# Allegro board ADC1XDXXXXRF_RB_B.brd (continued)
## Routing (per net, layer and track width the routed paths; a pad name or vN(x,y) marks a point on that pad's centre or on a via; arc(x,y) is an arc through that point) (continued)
FMC_DID-4: length 142.1
  TOP w0.102: v1(115.72,88.75) U5.T3
  SIG2 w0.102: v1(115.72,88.75) 115.32,88.34 102.93,88.34 101.92,89.35 83.81,89.35 83.71,89.45 83.71,89.52 83.48,89.74 83.11,89.74 82.89,89.52 82.89,89.45 82.79,89.35 82.59,89.35 82.49,89.45 82.49,89.52 82.27,89.74 81.89,89.74 81.67,89.52 81.67,89.45 81.57,89.35 81.37,89.35 81.27,89.45 81.27,89.52 81.05,89.74 80.67,89.74 80.45,89.52 80.45,89.45 80.35,89.35 80.15,89.35 80.05,89.45 80.05,89.52 79.83,89.74 79.46,89.74 79.23,89.52 79.23,89.45 79.13,89.35 78.37,89.35 77.93,88.9 77.93,88.08 77.83,87.98 76.7,87.98 76.48,87.76 76.48,87.39 76.7,87.17 77.83,87.17 77.93,87.06 77.93,86.86 77.83,86.76 76.7,86.76 76.48,86.54 76.48,86.17 76.7,85.95 77.83,85.95 77.93,85.85 77.93,84.94 77.62,84.63 75.13,84.63 75.03,84.73 75.03,85.1 74.81,85.32 74.44,85.32 74.22,85.1 74.22,84.73 74.12,84.63 73.91,84.63 73.81,84.73 73.81,85.1 73.59,85.32 73.22,85.32 73,85.1 73,84.73 72.9,84.63 72.69,84.63 72.59,84.73 72.59,85.1 72.37,85.32 72,85.32 71.78,85.1 71.78,84.73 71.68,84.63 71.48,84.63 71.37,84.73 71.37,85.1 71.15,85.32 70.78,85.32 70.56,85.1 70.56,84.73 70.46,84.63 70.26,84.63 70.15,84.73 70.15,85.1 69.93,85.32 69.56,85.32 69.34,85.1 69.34,84.73 69.24,84.63 69.04,84.63 68.94,84.73 68.94,85.1 68.72,85.32 68.34,85.32 68.12,85.1 68.12,84.73 68.02,84.63 67.82,84.63 67.72,84.73 67.72,85.1 67.5,85.32 67.12,85.32 66.9,85.1 66.9,84.73 66.8,84.63 66.6,84.63 66.5,84.73 66.5,85.1 66.28,85.32 65.9,85.32 65.68,85.1 65.68,84.73 65.58,84.63 65.38,84.63 65.28,84.73 65.28,85.1 65.06,85.32 64.69,85.32 64.47,85.1 64.47,84.73 64.36,84.63 64.16,84.63 64.06,84.73 64.06,85.1 63.84,85.32 63.47,85.32 63.25,85.1 63.25,84.73 63.14,84.63 62.94,84.63 62.84,84.73 62.84,85.1 62.62,85.32 62.25,85.32 62.03,85.1 62.03,84.73 61.93,84.63 61.72,84.63 61.62,84.73 61.62,85.1 61.4,85.32 61.03,85.32 60.81,85.1 60.81,84.73 60.71,84.63 60.5,84.63 60.4,84.73 60.4,85.1 60.18,85.32 59.81,85.32 59.59,85.1 59.59,84.73 59.49,84.63 59.28,84.63 59.18,84.73 59.18,85.1 58.96,85.32 58.59,85.32 58.37,85.1 58.37,84.73 58.27,84.63 58.06,84.63 57.96,84.73 57.96,85.1 57.74,85.32 57.37,85.32 57.15,85.1 57.15,84.73 57.05,84.63 56.85,84.63 56.74,84.73 56.74,85.1 56.52,85.32 56.15,85.32 55.93,85.1 55.93,84.73 55.83,84.63 55.63,84.63 55.52,84.73 55.52,85.1 55.3,85.32 54.93,85.32 54.71,85.1 54.71,84.73 54.61,84.63 54.41,84.63 54.31,84.73 54.31,85.1 54.08,85.32 53.71,85.32 53.49,85.1 53.49,84.73 53.39,84.63 53.19,84.63 53.09,84.73 53.09,85.1 52.87,85.32 52.49,85.32 52.27,85.1 52.27,84.73 52.17,84.63 51.97,84.63 51.87,84.73 51.87,85.1 51.65,85.32 51.27,85.32 51.05,85.1 51.05,84.73 50.95,84.63 50.75,84.63 50.65,84.73 50.65,85.1 50.43,85.32 50.06,85.32 49.83,85.1 49.83,84.73 49.73,84.63 49.53,84.63 49.43,84.73 49.43,85.1 49.21,85.32 48.84,85.32 48.62,85.1 48.62,84.73 48.51,84.63 48.31,84.63 48.21,84.73 48.21,85.1 47.99,85.32 47.62,85.32 47.4,85.1 47.4,84.73 47.29,84.63 47.09,84.63 46.99,84.73 46.99,85.1 46.77,85.32 46.4,85.32 46.18,85.1 46.18,84.73 46.08,84.63 11.33,84.63 v3(10.79,85.17)
  BOTTOM w0.102: FMC.D12 v3(10.79,85.17)
FMC_DID-5: length 142.2
  TOP w0.102: v1(114.72,87.74) U5.U2
  SIG2 w0.102: v3(9.53,83.9) 10.06,83.36 46.08,83.36 46.18,83.46 46.18,83.8 46.4,84.02 46.77,84.02 46.99,83.8 46.99,83.46 47.09,83.36 47.29,83.36 47.4,83.46 47.4,83.8 47.62,84.02 47.99,84.02 48.21,83.8 48.21,83.46 48.31,83.36 48.51,83.36 48.62,83.46 48.62,83.8 48.84,84.02 49.21,84.02 49.43,83.8 49.43,83.46 49.53,83.36 49.73,83.36 49.83,83.46 49.83,83.8 50.06,84.02 50.43,84.02 50.65,83.8 50.65,83.46 50.75,83.36 50.95,83.36 51.05,83.46 51.05,83.8 51.27,84.02 51.65,84.02 51.87,83.8 51.87,83.46 51.97,83.36 52.17,83.36 52.27,83.46 52.27,83.8 52.49,84.02 52.87,84.02 53.09,83.8 53.09,83.46 53.19,83.36 53.39,83.36 53.49,83.46 53.49,83.8 53.71,84.02 54.08,84.02 54.31,83.8 54.31,83.46 54.41,83.36 54.61,83.36 54.71,83.46 54.71,83.8 54.93,84.02 55.3,84.02 55.52,83.8 55.52,83.46 55.63,83.36 55.83,83.36 55.93,83.46 55.93,83.8 56.15,84.02 56.52,84.02 56.74,83.8 56.74,83.46 56.85,83.36 57.05,83.36 57.15,83.46 57.15,83.8 57.37,84.02 57.74,84.02 57.96,83.8 57.96,83.46 58.06,83.36 58.27,83.36 58.37,83.46 58.37,83.8 58.59,84.02 58.96,84.02 59.18,83.8 59.18,83.46 59.28,83.36 59.49,83.36 59.59,83.46 59.59,83.8 59.81,84.02 60.18,84.02 60.4,83.8 60.4,83.46 60.5,83.36 62.64,83.36 62.75,83.46 62.75,83.8 62.97,84.02 63.34,84.02 63.56,83.8 63.56,83.46 63.66,83.36 63.86,83.36 63.96,83.46 63.96,83.8 64.19,84.02 64.56,84.02 64.78,83.8 64.78,83.46 64.88,83.36 65.08,83.36 65.18,83.46 65.18,83.8 65.4,84.02 65.78,84.02 66,83.8 66,83.46 66.1,83.36 66.3,83.36 66.4,83.46 66.4,83.8 66.62,84.02 67,84.02 67.22,83.8 67.22,83.46 67.32,83.36 67.52,83.36 67.62,83.46 67.62,83.8 67.84,84.02 68.21,84.02 68.43,83.8 68.43,83.46 68.54,83.36 68.74,83.36 68.84,83.46 68.84,83.8 69.06,84.02 69.43,84.02 69.65,83.8 69.65,83.46 69.76,83.36 69.96,83.36 70.06,83.46 70.06,83.8 70.28,84.02 70.65,84.02 70.87,83.8 70.87,83.46 70.97,83.36 71.18,83.36 71.28,83.46 71.28,83.8 71.5,84.02 71.87,84.02 72.09,83.8 72.09,83.46 72.19,83.36 72.4,83.36 72.5,83.46 72.5,83.8 72.72,84.02 73.09,84.02 73.31,83.8 73.31,83.46 73.41,83.36 73.62,83.36 73.72,83.46 73.72,83.8 73.94,84.02 74.31,84.02 74.53,83.8 74.53,83.46 74.63,83.36 74.84,83.36 74.94,83.46 74.94,83.8 75.16,84.02 75.53,84.02 75.75,83.8 75.75,83.46 75.85,83.36 76.05,83.36 76.16,83.46 76.16,83.8 76.38,84.02 76.75,84.02 76.97,83.8 76.97,83.46 77.07,83.36 77.67,83.36 79.2,84.89 79.2,86.42 79.42,86.64 83.31,86.64 83.41,86.74 83.41,86.95 83.31,87.05 79.42,87.05 79.2,87.27 79.2,87.94 79.6,88.34 101.7,88.34 102.7,87.34 114.33,87.34 114.72,87.73 v1(114.72,87.74)
  BOTTOM w0.102: FMC.C11 v3(9.53,83.9)
FMC_DID-6: length 142.1
  TOP w0.102: v1(113.72,86.74) U5.V1
  SIG3 w0.102: v1(113.72,86.74) 113.82,86.64 114.17,86.64 114.3,86.77 114.3,86.87 114.03,87.14 77.71,87.14 76.89,86.31 76.89,85.75 76.96,85.67 77.45,85.67 77.57,85.55 77.57,85.39 v3(77.34,85.17)
  BOTTOM w0.102: FMC.H14 17.27,87.83 52.17,87.83 56.62,92.28 64.29,92.28 65,91.57 65,70.62 65.54,70.08 74.57,70.08 74.83,70.34 74.83,85.81 75.31,86.28 76.66,86.28 77.14,85.81 77.14,85.37 v3(77.34,85.17)
FMC_DID-7: length 142.1
  TOP w0.102: U5.P6 119.2,91.24 v1(118.71,90.75)
  SIG1 w0.102: v1(118.71,90.75) 118.83,90.75 119.1,90.47 119.1,89.56 118.88,89.34 117.43,89.34 117.12,89.04 117.12,88.55 116.91,88.34 105.24,88.34 97.52,96.06 58.06,96.06 57.96,96.16 57.96,96.4 57.74,96.62 57.36,96.62 57.14,96.4 57.14,96.16 57.04,96.06 56.84,96.06 56.74,96.16 56.74,96.4 56.52,96.62 56.15,96.62 55.92,96.4 55.92,96.16 55.82,96.06 55.62,96.06 55.52,96.16 55.52,96.4 55.3,96.62 54.93,96.62 54.71,96.4 54.71,96.16 54.6,96.06 54.4,96.06 54.3,96.16 54.3,96.4 54.08,96.62 53.71,96.62 53.49,96.4 53.49,96.16 53.38,96.06 53.18,96.06 53.08,96.16 53.08,96.4 52.86,96.62 52.49,96.62 52.27,96.4 52.27,96.16 52.17,96.06 51.96,96.06 51.86,96.16 51.86,96.4 51.64,96.62 51.27,96.62 51.05,96.4 51.05,96.16 50.95,96.06 50.74,96.06 50.64,96.16 50.64,96.4 50.42,96.62 50.05,96.62 49.83,96.4 49.83,96.16 49.73,96.06 49.52,96.06 49.42,96.16 49.42,96.4 49.2,96.62 48.83,96.62 48.61,96.4 48.61,96.16 48.51,96.06 48.3,96.06 48.2,96.16 48.2,96.4 47.98,96.62 47.61,96.62 47.39,96.4 47.39,96.16 47.29,96.06 47.09,96.06 46.98,96.16 46.98,96.4 46.76,96.62 46.39,96.62 46.17,96.4 46.17,96.16 46.07,96.06 11.75,96.06 11.12,95.43 9.75,95.43 8.76,94.45 8.76,88.51 9.03,88.24 15.44,88.24 15.77,87.9 15.77,86.24 15.44,85.9 14.68,85.9 14.61,85.98 v3(14.61,86.44)
  BOTTOM w0.102: FMC.G13 v3(14.61,86.44)
FMC_DID-8: length 142.1
  TOP w0.102: v1(115.72,89.75) U5.R3
  SIG2 w0.102: v1(115.72,89.75) 115.6,89.75 114.99,90.35 103.46,90.35 102.46,91.35 76.26,91.35 72.66,87.76 58.06,87.76 57.96,87.86 57.96,89.37 57.74,89.59 57.37,89.59 57.15,89.37 57.15,87.86 57.05,87.76 56.85,87.76 56.74,87.86 56.74,89.37 56.52,89.59 56.15,89.59 55.93,89.37 55.93,87.86 55.83,87.76 55.63,87.76 55.52,87.86 55.52,89.37 55.3,89.59 54.93,89.59 54.71,89.37 54.71,87.86 54.61,87.76 54.41,87.76 54.31,87.86 54.31,89.37 54.08,89.59 53.71,89.59 53.49,89.37 53.49,87.86 53.39,87.76 53.19,87.76 53.09,87.86 53.09,89.37 52.87,89.59 52.49,89.59 52.27,89.37 52.27,87.86 52.17,87.76 51.97,87.76 51.87,87.86 51.87,89.37 51.65,89.59 51.27,89.59 51.05,89.37 51.05,87.86 50.95,87.76 50.75,87.76 50.65,87.86 50.65,89.37 50.43,89.59 50.06,89.59 49.83,89.37 49.83,87.86 49.73,87.76 49.53,87.76 49.43,87.86 49.43,89.37 49.21,89.59 48.84,89.59 48.62,89.37 48.62,87.86 48.51,87.76 48.31,87.76 48.21,87.86 48.21,89.37 47.99,89.59 47.62,89.59 47.4,89.37 47.4,87.86 47.29,87.76 47.09,87.76 46.99,87.86 46.99,89.37 46.77,89.59 46.4,89.59 46.18,89.37 46.18,87.86 46.08,87.76 16.24,87.76 15.55,88.44 11.58,88.44 11.51,88.52 11.51,88.9 11.58,88.98 v3(12.06,88.98)
  BOTTOM w0.102: FMC.D15 v3(12.06,88.98)
FMC_DID-9: length 142.1
  TOP w0.102: v1(113.72,89.75) U5.R1
  SIG2 w0.102: v3(10.79,87.71) 10.52,87.71 10.44,87.63 10.44,87.25 10.52,87.17 13.55,87.17 14,86.72 14,86.19 14.26,85.93 46.08,85.93 46.18,86.03 46.18,86.93 46.4,87.15 46.77,87.15 46.99,86.93 46.99,86.03 47.09,85.93 47.29,85.93 47.4,86.03 47.4,86.93 47.62,87.15 47.99,87.15 48.21,86.93 48.21,86.03 48.31,85.93 48.51,85.93 48.62,86.03 48.62,86.93 48.84,87.15 49.21,87.15 49.43,86.93 49.43,86.03 49.53,85.93 49.73,85.93 49.83,86.03 49.83,86.93 50.06,87.15 50.43,87.15 50.65,86.93 50.65,86.03 50.75,85.93 50.95,85.93 51.05,86.03 51.05,86.93 51.27,87.15 51.65,87.15 51.87,86.93 51.87,86.03 51.97,85.93 52.17,85.93 52.27,86.03 52.27,86.93 52.49,87.15 52.87,87.15 53.09,86.93 53.09,86.03 53.19,85.93 53.39,85.93 53.49,86.03 53.49,86.93 53.71,87.15 54.08,87.15 54.31,86.93 54.31,86.03 54.41,85.93 54.61,85.93 54.71,86.03 54.71,86.93 54.93,87.15 55.3,87.15 55.52,86.93 55.52,86.03 55.63,85.93 58.28,85.93 58.39,86.03 58.39,86.83 58.61,87.05 58.98,87.05 59.2,86.83 59.2,86.03 59.3,85.93 59.5,85.93 59.6,86.03 59.6,86.83 59.83,87.05 60.2,87.05 60.42,86.83 60.42,86.03 60.52,85.93 60.72,85.93 60.82,86.03 60.82,86.83 61.04,87.05 61.42,87.05 61.64,86.83 61.64,86.03 61.74,85.93 61.94,85.93 62.04,86.03 62.04,86.83 62.26,87.05 62.64,87.05 62.86,86.83 62.86,86.03 62.96,85.93 63.16,85.93 63.26,86.03 63.26,86.83 63.48,87.05 63.85,87.05 64.08,86.83 64.08,86.03 64.18,85.93 64.38,85.93 64.48,86.03 64.48,86.83 64.7,87.05 65.07,87.05 65.29,86.83 65.29,86.03 65.4,85.93 65.6,85.93 65.7,86.03 65.7,86.8 65.92,87.02 66.29,87.02 66.51,86.8 66.51,86.03 66.62,85.93 66.82,85.93 66.92,86.03 66.92,86.8 67.14,87.02 67.51,87.02 67.73,86.8 67.73,86.03 67.83,85.93 68.04,85.93 68.14,86.03 68.14,86.8 68.36,87.02 68.73,87.02 68.95,86.8 68.95,86.03 69.05,85.93 73.6,85.93 78.02,90.35 102.17,90.35 103.17,89.35 113.58,89.35 113.72,89.49 v1(113.72,89.75)
  BOTTOM w0.102: FMC.C15 v3(10.79,87.71)
FMC_DID-10: length 142.2
  TOP w0.102: v1(116.71,90.75) 117.2,91.24 U5.P4
  SIG2 w0.102: v1(116.71,90.75) 116.71,90.76 116.11,91.35 103.67,91.35 102.66,92.35 64.38,92.35 64.27,92.46 64.27,93.68 64.05,93.9 63.68,93.9 63.46,93.68 63.46,92.46 63.36,92.35 63.16,92.35 63.05,92.46 63.05,93.68 62.83,93.9 62.46,93.9 62.24,93.68 62.24,92.46 62.14,92.35 61.94,92.35 61.84,92.46 61.84,93.68 61.62,93.9 61.24,93.9 61.02,93.68 61.02,92.46 60.92,92.35 60.72,92.35 60.62,92.46 60.62,93.68 60.4,93.9 60.02,93.9 59.8,93.68 59.8,92.46 59.7,92.35 59.5,92.35 59.4,92.46 59.4,93.68 59.18,93.9 58.8,93.9 58.58,93.68 58.58,92.46 58.48,92.35 58.28,92.35 58.18,92.46 58.18,93.68 57.96,93.9 57.59,93.9 57.37,93.68 57.37,92.46 57.26,92.35 57.06,92.35 56.96,92.46 56.96,93.68 56.74,93.9 56.37,93.9 56.15,93.68 56.15,92.46 56.04,92.35 55.84,92.35 55.74,92.46 55.74,93.68 55.52,93.9 55.15,93.9 54.93,93.68 54.93,92.46 54.83,92.35 54.62,92.35 54.52,92.46 54.52,93.68 54.3,93.9 53.93,93.9 53.71,93.68 53.71,92.46 53.61,92.35 53.4,92.35 53.3,92.46 53.3,93.68 53.08,93.9 52.71,93.9 52.49,93.68 52.49,92.46 52.39,92.35 52.18,92.35 52.08,92.46 52.08,93.68 51.86,93.9 51.49,93.9 51.27,93.68 51.27,92.46 51.17,92.35 50.96,92.35 50.86,92.46 50.86,93.68 50.64,93.9 50.27,93.9 50.05,93.68 50.05,92.46 49.95,92.35 49.75,92.35 49.64,92.46 49.64,93.68 49.42,93.9 49.05,93.9 48.83,93.68 48.83,92.46 48.73,92.35 48.53,92.35 48.42,92.46 48.42,93.68 48.2,93.9 47.83,93.9 47.61,93.68 47.61,92.46 47.51,92.35 46.78,92.35 45.41,90.98 16.64,90.98 16.54,91.08 16.54,91.41 16.64,91.52 v3(17.14,91.52)
  BOTTOM w0.102: v3(17.14,91.52) FMC.H17
FMC_DID-11: length 142.1
  TOP w0.102: U5.P2 115.2,91.24 v1(114.7,90.75)
  SIG3 w0.102: v1(114.7,90.75) 114.97,90.75 115.11,90.6 115.11,90.47 114.99,90.35 76.37,90.35 75,88.98 v3(74.96,88.98)
  BOTTOM w0.102: v3(74.96,88.98) 75.16,88.77 75.16,88.44 73.56,86.84 73.56,71.91 73.07,71.42 66.63,71.42 66.27,71.78 66.27,92.99 65.71,93.55 56.08,93.55 51.64,89.1 15.65,89.1 15.24,89.51 FMC.G16
FMC_DQ+0: length 142
  TOP w0.102: U5.C4 117.22,102.25 v1(116.71,102.76)
  SIG2 w0.102: v1(116.71,102.76) 116.71,102.44 116.62,102.36 103.82,102.36 94.88,111.3 61.72,111.3 61.62,111.4 61.62,111.62 61.4,111.84 61.03,111.84 60.81,111.62 60.81,111.4 60.71,111.3 60.5,111.3 60.4,111.4 60.4,111.62 60.18,111.84 59.81,111.84 59.59,111.62 59.59,111.4 59.49,111.3 59.28,111.3 59.18,111.4 59.18,111.62 58.96,111.84 58.59,111.84 58.37,111.62 58.37,111.4 58.27,111.3 58.06,111.3 57.96,111.4 57.96,111.62 57.74,111.84 57.37,111.84 57.15,111.62 57.15,111.4 57.05,111.3 56.85,111.3 56.74,111.4 56.74,111.62 56.52,111.84 56.15,111.84 55.93,111.62 55.93,111.4 55.83,111.3 55.63,111.3 55.52,111.4 55.52,111.62 55.3,111.84 54.93,111.84 54.71,111.62 54.71,111.4 54.61,111.3 54.41,111.3 54.31,111.4 54.31,111.62 54.08,111.84 53.71,111.84 53.49,111.62 53.49,111.4 53.39,111.3 53.19,111.3 53.09,111.4 53.09,111.62 52.87,111.84 52.49,111.84 52.27,111.62 52.27,111.4 52.17,111.3 51.97,111.3 51.87,111.4 51.87,111.62 51.65,111.84 51.27,111.84 51.05,111.62 51.05,111.4 50.95,111.3 50.75,111.3 50.65,111.4 50.65,111.62 50.43,111.84 50.06,111.84 49.83,111.62 49.83,111.4 49.73,111.3 49.53,111.3 49.43,111.4 49.43,111.62 49.21,111.84 48.84,111.84 48.62,111.62 48.62,111.4 48.51,111.3 48.31,111.3 48.21,111.4 48.21,111.62 47.99,111.84 47.62,111.84 47.4,111.62 47.4,111.4 47.29,111.3 47.09,111.3 46.99,111.4 46.99,111.62 46.77,111.84 46.4,111.84 46.18,111.62 46.18,111.4 46.08,111.3 9.87,111.3 8.79,110.22 8.79,101.21 9.06,100.94 12.29,100.94 12.6,100.63 12.6,100.02 12.95,99.67 17.14,99.67 17.25,99.57 17.25,99.24 v3(17.14,99.14)
  BOTTOM w0.102: v3(17.14,99.14) FMC.J24
FMC_DQ+1: length 142.2
  TOP w0.102: v1(117.71,102.76) 118.22,102.25 U5.C5
  SIG1 w0.102: v3(13.34,97.87) 12.8,98.4 9.06,98.4 8.79,98.67 8.79,117.36 9.09,117.65 103.67,117.65 116.31,105.01 116.31,102.59 116.54,102.36 117.31,102.36 v1(117.71,102.76)
  BOTTOM w0.102: FMC.F22 v3(13.34,97.87)
FMC_DQ+2: length 142
  TOP w0.102: U5.E6 119.22,100.24 v1(118.71,100.75)
  SIG2 w0.102: v1(118.71,100.75) 118.31,101.15 118.31,103.06 118.01,103.36 104.02,103.36 94.8,112.57 50.75,112.57 50.65,112.67 50.65,112.91 50.43,113.13 50.06,113.13 49.83,112.91 49.83,112.67 49.73,112.57 49.53,112.57 49.43,112.67 49.43,112.91 49.21,113.13 48.84,113.13 48.62,112.91 48.62,112.67 48.51,112.57 48.31,112.57 48.21,112.67 48.21,112.91 47.99,113.13 47.62,113.13 47.4,112.91 47.4,112.67 47.29,112.57 47.09,112.57 46.99,112.67 46.99,112.91 46.77,113.13 46.4,113.13 46.18,112.91 46.18,112.67 46.08,112.57 8.83,112.57 7.52,111.26 7.52,98.12 9.42,96.22 9.42,95.62 9.82,95.22 10.4,95.22 11.02,95.85 11.53,95.85 v3(12.06,95.31)
  BOTTOM w0.102: FMC.E21 v3(12.06,95.31)
FMC_DQ+3: length 142.2
  TOP w0.102: v1(118.72,97.74) U5.G6
  SIG2 w0.102: v3(14.61,100.41) 14,100.41 13.84,100.56 13.84,100.81 13.97,100.94 46.16,100.94 46.38,101.16 46.38,101.37 46.48,101.47 46.69,101.47 46.79,101.37 46.79,101.16 47.01,100.94 47.38,100.94 47.6,101.16 47.6,101.37 47.7,101.47 47.9,101.47 48.01,101.37 48.01,101.16 48.23,100.94 48.6,100.94 48.82,101.16 48.82,101.37 48.92,101.47 49.12,101.47 49.23,101.37 49.23,101.16 49.45,100.94 49.82,100.94 50.04,101.16 50.04,101.37 50.14,101.47 50.34,101.47 50.44,101.37 50.44,101.16 50.66,100.94 51.04,100.94 51.26,101.16 51.26,101.37 51.36,101.47 51.56,101.47 51.66,101.37 51.66,101.16 51.88,100.94 52.26,100.94 52.48,101.16 52.48,101.37 52.58,101.47 52.78,101.47 52.88,101.37 52.88,101.16 53.1,100.94 53.48,100.94 53.7,101.16 53.7,101.37 53.8,101.47 54,101.47 54.1,101.37 54.1,101.16 54.32,100.94 54.69,100.94 54.91,101.16 54.91,101.37 55.02,101.47 55.22,101.47 55.32,101.37 55.32,101.16 55.54,100.94 55.91,100.94 56.13,101.16 56.13,101.37 56.24,101.47 56.44,101.47 56.54,101.37 56.54,101.16 56.76,100.94 57.13,100.94 57.35,101.16 57.35,101.37 57.45,101.47 57.66,101.47 57.76,101.37 57.76,101.16 57.98,100.94 58.35,100.94 58.57,101.16 58.57,101.37 58.67,101.47 58.88,101.47 58.98,101.37 58.98,101.16 59.2,100.94 59.57,100.94 59.79,101.16 59.79,101.37 59.89,101.47 60.1,101.47 60.2,101.37 60.2,101.16 60.42,100.94 60.79,100.94 61.01,101.16 61.01,101.37 61.11,101.47 61.32,101.47 61.42,101.37 61.42,101.16 61.64,100.94 62.01,100.94 62.23,101.16 62.23,101.37 62.33,101.47 62.53,101.47 62.64,101.37 62.64,101.16 62.86,100.94 63.23,100.94 63.45,101.16 63.45,101.37 63.55,101.47 63.75,101.47 63.86,101.37 63.86,101.16 64.08,100.94 64.45,100.94 64.67,101.16 64.67,101.37 64.77,101.47 64.97,101.47 65.07,101.37 65.07,101.16 65.3,100.94 65.67,100.94 65.89,101.16 65.89,101.37 65.99,101.47 66.19,101.47 66.29,101.37 66.29,101.16 66.51,100.94 66.89,100.94 67.11,101.16 67.11,101.37 67.21,101.47 67.41,101.47 67.51,101.37 67.51,101.16 67.73,100.94 68.11,100.94 68.33,101.16 68.33,101.37 68.43,101.47 68.63,101.47 68.73,101.37 68.73,101.16 68.95,100.94 69.32,100.94 69.55,101.16 69.55,101.37 69.65,101.47 69.85,101.47 69.95,101.37 69.95,101.16 70.17,100.94 70.54,100.94 70.76,101.16 70.76,101.37 70.87,101.47 71.07,101.47 71.17,101.37 71.17,101.16 71.39,100.94 71.76,100.94 71.98,101.16 71.98,101.37 72.09,101.47 72.29,101.47 72.39,101.37 72.39,101.16 72.61,100.94 72.98,100.94 73.2,101.16 73.2,101.37 73.3,101.47 73.51,101.47 73.61,101.37 73.61,101.16 73.83,100.94 74.2,100.94 74.42,101.16 74.42,101.37 74.52,101.47 74.73,101.47 74.83,101.37 74.83,101.16 75.05,100.94 75.42,100.94 75.64,101.16 75.64,101.37 75.74,101.47 75.95,101.47 76.05,101.37 76.05,101.16 76.27,100.94 76.64,100.94 76.86,101.16 76.86,101.37 76.96,101.47 77.17,101.47 77.27,101.37 77.27,101.16 77.49,100.94 77.86,100.94 78.08,101.16 78.08,101.37 78.18,101.47 78.38,101.47 78.49,101.37 78.49,101.16 78.71,100.94 79.08,100.94 79.3,101.16 79.3,101.37 79.4,101.47 79.6,101.47 79.71,101.37 79.71,101.16 79.93,100.94 80.3,100.94 80.52,101.16 80.52,101.37 80.62,101.47 80.82,101.47 80.92,101.37 80.92,101.16 81.14,100.94 81.52,100.94 81.74,101.16 81.74,101.37 81.84,101.47 82.04,101.47 82.14,101.37 82.14,101.16 82.36,100.94 82.74,100.94 82.96,101.16 82.96,101.37 83.06,101.47 83.26,101.47 83.36,101.37 83.36,101.16 83.58,100.94 83.96,100.94 84.18,101.16 84.18,101.37 84.28,101.47 84.48,101.47 84.58,101.37 84.58,101.16 84.8,100.94 85.17,100.94 85.39,101.16 85.39,101.37 85.5,101.47 85.7,101.47 85.8,101.37 85.8,101.16 86.02,100.94 86.39,100.94 86.61,101.16 86.61,101.37 86.72,101.47 86.92,101.47 87.02,101.37 87.02,101.16 87.24,100.94 87.61,100.94 87.83,101.16 87.83,101.37 87.93,101.47 88.14,101.47 88.24,101.37 88.24,101.16 88.46,100.94 97.51,100.94 104.31,94.15 114.87,94.15 115.87,93.15 119.98,93.15 120.32,93.49 120.32,97.06 120.03,97.35 119.11,97.35 v1(118.72,97.74)
  BOTTOM w0.102: FMC.F25 v3(14.61,100.41)
FMC_DQ+4: length 142
  TOP w0.102: U5.D3 116.22,101.24 v1(115.71,101.75)
  SIG1 w0.102: v3(13.34,100.41) 12.8,100.94 10.33,100.94 10.06,101.21 10.06,116.15 10.3,116.38 46.06,116.38 46.16,116.48 46.16,116.8 46.38,117.02 46.76,117.02 46.98,116.8 46.98,116.48 47.08,116.38 47.28,116.38 47.38,116.48 47.38,116.8 47.6,117.02 47.97,117.02 48.2,116.8 48.2,116.48 48.3,116.38 48.5,116.38 48.6,116.48 48.6,116.8 48.82,117.02 49.19,117.02 49.41,116.8 49.41,116.48 49.52,116.38 49.72,116.38 49.82,116.48 49.82,116.8 50.04,117.02 50.41,117.02 50.63,116.8 50.63,116.48 50.74,116.38 50.94,116.38 51.04,116.48 51.04,116.8 51.26,117.02 51.63,117.02 51.85,116.8 51.85,116.48 51.95,116.38 52.16,116.38 52.26,116.48 52.26,116.8 52.48,117.02 52.85,117.02 53.07,116.8 53.07,116.48 53.17,116.38 53.38,116.38 53.48,116.48 53.48,116.8 53.7,117.02 54.07,117.02 54.29,116.8 54.29,116.48 54.39,116.38 54.6,116.38 54.7,116.48 54.7,116.8 54.92,117.02 55.29,117.02 55.51,116.8 55.51,116.48 55.61,116.38 55.82,116.38 55.92,116.48 55.92,116.8 56.14,117.02 56.51,117.02 56.73,116.8 56.73,116.48 56.83,116.38 57.03,116.38 57.14,116.48 57.14,116.8 57.36,117.02 57.73,117.02 57.95,116.8 57.95,116.48 58.05,116.38 102.94,116.38 115.31,104.02 115.31,102.16 v1(115.71,101.75)
  BOTTOM w0.102: FMC.E24 v3(13.34,100.41)
FMC_DQ+5: length 142
  TOP w0.102: v1(114.7,102.76) 115.21,102.25 U5.C2
  SIG1 w0.102: v1(114.7,102.76) 114.31,103.15 114.31,103.48 102.67,115.11 66.58,115.11 66.48,115.21 66.48,115.5 66.26,115.72 65.89,115.72 65.67,115.5 65.67,115.21 65.57,115.11 65.37,115.11 65.26,115.21 65.26,115.5 65.04,115.72 64.67,115.72 64.45,115.5 64.45,115.21 64.35,115.11 64.15,115.11 64.04,115.21 64.04,115.5 63.82,115.72 63.45,115.72 63.23,115.5 63.23,115.21 63.13,115.11 62.93,115.11 62.83,115.21 62.83,115.5 62.61,115.72 62.23,115.72 62.01,115.5 62.01,115.21 61.91,115.11 61.71,115.11 61.61,115.21 61.61,115.5 61.39,115.72 61.01,115.72 60.79,115.5 60.79,115.21 60.69,115.11 60.49,115.11 60.39,115.21 60.39,115.5 60.17,115.72 59.79,115.72 59.57,115.5 59.57,115.21 59.47,115.11 59.27,115.11 59.17,115.21 59.17,115.5 58.95,115.72 58.58,115.72 58.36,115.5 58.36,115.21 58.25,115.11 58.05,115.11 57.95,115.21 57.95,115.5 57.73,115.72 57.36,115.72 57.14,115.5 57.14,115.21 57.03,115.11 56.83,115.11 56.73,115.21 56.73,115.5 56.51,115.72 56.14,115.72 55.92,115.5 55.92,115.21 55.82,115.11 55.61,115.11 55.51,115.21 55.51,115.5 55.29,115.72 54.92,115.72 54.7,115.5 54.7,115.21 54.6,115.11 54.39,115.11 54.29,115.21 54.29,115.5 54.07,115.72 53.7,115.72 53.48,115.5 53.48,115.21 53.38,115.11 53.17,115.11 53.07,115.21 53.07,115.5 52.85,115.72 52.48,115.72 52.26,115.5 52.26,115.21 52.16,115.11 51.95,115.11 51.85,115.21 51.85,115.5 51.63,115.72 51.26,115.72 51.04,115.5 51.04,115.21 50.94,115.11 50.74,115.11 50.63,115.21 50.63,115.5 50.41,115.72 50.04,115.72 49.82,115.5 49.82,115.21 49.72,115.11 49.52,115.11 49.41,115.21 49.41,115.5 49.19,115.72 48.82,115.72 48.6,115.5 48.6,115.21 48.5,115.11 48.3,115.11 48.2,115.21 48.2,115.5 47.97,115.72 47.6,115.72 47.38,115.5 47.38,115.21 47.28,115.11 47.08,115.11 46.98,115.21 46.98,115.5 46.76,115.72 46.38,115.72 46.16,115.5 46.16,115.21 46.06,115.11 11.57,115.11 11.33,114.88 11.33,106.27 11.57,106.02 19.15,106.02 v3(19.68,105.49)
  BOTTOM w0.102: FMC.K28 v3(19.68,105.49)
FMC_DQ+6: length 142
  TOP w0.102: v1(116.72,98.75) U5.F4
  SIG1 w0.102: v3(18.41,104.22) 18.95,104.75 46.15,104.75 46.37,104.97 46.37,106.02 46.48,106.12 46.68,106.12 46.78,106.02 46.78,104.97 47,104.75 47.37,104.75 47.59,104.97 47.59,106.02 47.7,106.12 47.9,106.12 48,106.02 48,104.97 48.22,104.75 48.59,104.75 48.81,104.97 48.81,106.02 48.91,106.12 49.12,106.12 49.22,106.02 49.22,104.97 49.44,104.75 49.81,104.75 50.03,104.97 50.03,106.02 50.13,106.12 50.34,106.12 50.44,106.02 50.44,104.97 50.66,104.75 51.03,104.75 51.25,104.97 51.25,106.02 51.35,106.12 51.56,106.12 51.66,106.02 51.66,104.97 51.88,104.75 52.25,104.75 52.47,104.97 52.47,106.02 52.57,106.12 52.78,106.12 52.88,106.02 52.88,104.97 53.1,104.75 53.47,104.75 53.69,104.97 53.69,106.02 53.79,106.12 53.99,106.12 54.1,106.02 54.1,104.97 54.32,104.75 54.69,104.75 54.91,104.97 54.91,106.02 55.01,106.12 55.21,106.12 55.32,106.02 55.32,104.97 55.54,104.75 55.91,104.75 56.13,104.97 56.13,106.02 56.23,106.12 56.43,106.12 56.53,106.02 56.53,104.97 56.76,104.75 57.13,104.75 57.35,104.97 57.35,106.02 57.45,106.12 57.65,106.12 57.75,106.02 57.75,104.97 57.97,104.75 58.35,104.75 58.57,104.97 58.57,106.02 58.67,106.12 58.87,106.12 58.97,106.02 58.97,104.97 59.19,104.75 59.57,104.75 59.79,104.97 59.79,106.02 59.89,106.12 60.09,106.12 60.19,106.02 60.19,104.97 60.41,104.75 60.78,104.75 61,104.97 61,106.07 61.11,106.17 61.31,106.17 61.41,106.07 61.41,104.97 61.63,104.75 62,104.75 62.22,104.97 62.22,106.07 62.33,106.17 62.53,106.17 62.63,106.07 62.63,104.97 62.85,104.75 98.76,104.75 109.36,94.14 115.99,94.14 116.32,94.48 116.32,98.34 v1(116.72,98.75)
  BOTTOM w0.102: FMC.J27 v3(18.41,104.22)
FMC_DQ+7: length 142.1
  TOP w0.102: v1(116.72,97.74) U5.G4
  SIG2 w0.102: v3(14.61,104.22) 15.14,104.75 46.16,104.75 46.38,104.97 46.38,105.31 46.48,105.41 46.69,105.41 46.79,105.31 46.79,104.97 47.01,104.75 47.38,104.75 47.6,104.97 47.6,105.31 47.7,105.41 47.9,105.41 48.01,105.31 48.01,104.97 48.23,104.75 48.6,104.75 48.82,104.97 48.82,105.31 48.92,105.41 49.12,105.41 49.23,105.31 49.23,104.97 49.45,104.75 49.82,104.75 50.04,104.97 50.04,105.31 50.14,105.41 50.34,105.41 50.44,105.31 50.44,104.97 50.66,104.75 51.04,104.75 51.26,104.97 51.26,105.31 51.36,105.41 51.56,105.41 51.66,105.31 51.66,104.97 51.88,104.75 52.26,104.75 52.48,104.97 52.48,105.31 52.58,105.41 52.78,105.41 52.88,105.31 52.88,104.97 53.1,104.75 53.48,104.75 53.7,104.97 53.7,105.31 53.8,105.41 54,105.41 54.1,105.31 54.1,104.97 54.32,104.75 54.69,104.75 54.91,104.97 54.91,105.31 55.02,105.41 55.22,105.41 55.32,105.31 55.32,104.97 55.54,104.75 55.91,104.75 56.13,104.97 56.13,105.31 56.24,105.41 56.44,105.41 56.54,105.31 56.54,104.97 56.76,104.75 57.13,104.75 57.35,104.97 57.35,105.31 57.45,105.41 57.66,105.41 57.76,105.31 57.76,104.97 57.98,104.75 58.35,104.75 58.57,104.97 58.57,105.31 58.67,105.41 58.88,105.41 58.98,105.31 58.98,104.97 59.2,104.75 59.57,104.75 59.79,104.97 59.79,105.31 59.89,105.41 60.1,105.41 60.2,105.31 60.2,104.97 60.42,104.75 60.79,104.75 61.01,104.97 61.01,105.31 61.11,105.41 61.32,105.41 61.42,105.31 61.42,104.97 61.64,104.75 62.01,104.75 62.23,104.97 62.23,105.31 62.33,105.41 62.53,105.41 62.64,105.31 62.64,104.97 62.86,104.75 63.23,104.75 63.45,104.97 63.45,105.31 63.55,105.41 63.75,105.41 63.86,105.31 63.86,104.97 64.08,104.75 64.45,104.75 64.67,104.97 64.67,105.31 64.77,105.41 64.97,105.41 65.07,105.31 65.07,104.97 65.3,104.75 65.67,104.75 65.89,104.97 65.89,105.31 65.99,105.41 66.19,105.41 66.29,105.31 66.29,104.97 66.51,104.75 66.89,104.75 67.11,104.97 67.11,105.31 67.21,105.41 67.41,105.41 67.51,105.31 67.51,104.97 67.73,104.75 68.11,104.75 68.33,104.97 68.33,105.31 68.43,105.41 68.63,105.41 68.73,105.31 68.73,104.97 68.95,104.75 69.32,104.75 69.55,104.97 69.55,105.31 69.65,105.41 69.85,105.41 69.95,105.31 69.95,104.97 70.17,104.75 70.54,104.75 70.76,104.97 70.76,105.31 70.87,105.41 71.07,105.41 71.17,105.31 71.17,104.97 71.39,104.75 71.76,104.75 71.98,104.97 71.98,105.31 72.09,105.41 72.29,105.41 72.39,105.31 72.39,104.97 72.61,104.75 72.98,104.75 73.2,104.97 73.2,105.31 73.3,105.41 73.51,105.41 73.61,105.31 73.61,104.97 73.83,104.75 74.2,104.75 74.42,104.97 74.42,105.31 74.52,105.41 74.73,105.41 74.83,105.31 74.83,104.97 75.05,104.75 75.42,104.75 75.64,104.97 75.64,105.31 75.74,105.41 75.95,105.41 76.05,105.31 76.05,104.97 76.27,104.75 76.64,104.75 76.86,104.97 76.86,105.31 76.96,105.41 77.17,105.41 77.27,105.31 77.27,104.97 77.49,104.75 77.86,104.75 78.08,104.97 78.08,105.31 78.18,105.41 78.38,105.41 78.49,105.31 78.49,104.97 78.71,104.75 79.08,104.75 79.3,104.97 79.3,105.31 79.4,105.41 79.6,105.41 79.71,105.31 79.71,104.97 79.93,104.75 80.3,104.75 80.52,104.97 80.52,105.31 80.62,105.41 80.82,105.41 80.92,105.31 80.92,104.97 81.14,104.75 81.52,104.75 81.74,104.97 81.74,105.31 81.84,105.41 82.04,105.41 82.14,105.31 82.14,104.97 82.36,104.75 82.74,104.75 82.96,104.97 82.96,105.31 83.06,105.41 83.26,105.41 83.36,105.31 83.36,104.97 83.58,104.75 83.96,104.75 84.18,104.97 84.18,105.31 84.28,105.41 84.48,105.41 84.58,105.31 84.58,104.97 84.8,104.75 85.17,104.75 85.39,104.97 85.39,105.31 85.5,105.41 85.7,105.41 85.8,105.31 85.8,104.97 86.02,104.75 86.39,104.75 86.61,104.97 86.61,105.31 86.72,105.41 86.92,105.41 87.02,105.31 87.02,104.97 87.24,104.75 87.61,104.75 87.83,104.97 87.83,105.28 87.93,105.38 88.14,105.38 88.24,105.28 88.24,104.97 88.46,104.75 88.83,104.75 89.05,104.97 89.05,105.28 89.15,105.38 89.36,105.38 89.46,105.28 89.46,104.97 89.68,104.75 90.05,104.75 90.27,104.97 90.27,105.28 90.37,105.38 90.58,105.38 90.68,105.28 90.68,104.97 90.9,104.75 96.9,104.75 104.51,97.14 115.69,97.14 116.29,97.74 v1(116.72,97.74)
  BOTTOM w0.102: FMC.F28 v3(14.61,104.22)
FMC_DQ+8: length 142.2
  TOP w0.102: U5.E1 114.22,100.24 v1(113.71,100.75)
  SIG2 w0.102: v1(113.71,100.75) 113.31,100.36 103.71,100.36 95.3,108.76 88.54,108.76 88.44,108.86 88.44,109.08 88.22,109.3 87.85,109.3 87.63,109.08 87.63,108.86 87.53,108.76 87.33,108.76 87.22,108.86 87.22,109.08 87,109.3 86.63,109.3 86.41,109.08 86.41,108.86 86.31,108.76 86.11,108.76 86,108.86 86,109.08 85.78,109.3 85.41,109.3 85.19,109.08 85.19,108.86 85.09,108.76 84.89,108.76 84.79,108.86 84.79,109.08 84.56,109.3 84.19,109.3 83.97,109.08 83.97,108.86 83.87,108.76 83.67,108.76 83.57,108.86 83.57,109.08 83.35,109.3 82.97,109.3 82.75,109.08 82.75,108.86 82.65,108.76 82.45,108.76 82.35,108.86 82.35,109.08 82.13,109.3 81.75,109.3 81.53,109.08 81.53,108.86 81.43,108.76 81.23,108.76 81.13,108.86 81.13,109.08 80.91,109.3 80.54,109.3 80.31,109.08 80.31,108.86 80.21,108.76 80.01,108.76 79.91,108.86 79.91,109.08 79.69,109.3 79.32,109.3 79.1,109.08 79.1,108.86 78.99,108.76 78.79,108.76 78.69,108.86 78.69,109.1 78.47,109.32 78.1,109.32 77.88,109.1 77.88,108.86 77.77,108.76 77.57,108.76 77.47,108.86 77.47,109.1 77.25,109.32 76.88,109.32 76.66,109.1 76.66,108.86 76.56,108.76 76.35,108.76 76.25,108.86 76.25,109.1 76.03,109.32 75.66,109.32 75.44,109.1 75.44,108.86 75.34,108.76 75.13,108.76 75.03,108.86 75.03,109.1 74.81,109.32 74.44,109.32 74.22,109.1 74.22,108.86 74.12,108.76 73.91,108.76 73.81,108.86 73.81,109.1 73.59,109.32 73.22,109.32 73,109.1 73,108.86 72.9,108.76 72.69,108.76 72.59,108.86 72.59,109.1 72.37,109.32 72,109.32 71.78,109.1 71.78,108.86 71.68,108.76 71.48,108.76 71.37,108.86 71.37,109.1 71.15,109.32 70.78,109.32 70.56,109.1 70.56,108.86 70.46,108.76 70.26,108.76 70.15,108.86 70.15,109.1 69.93,109.32 69.56,109.32 69.34,109.1 69.34,108.86 69.24,108.76 69.04,108.76 68.94,108.86 68.94,109.1 68.72,109.32 68.34,109.32 68.12,109.1 68.12,108.86 68.02,108.76 67.82,108.76 67.72,108.86 67.72,109.1 67.5,109.32 67.12,109.32 66.9,109.1 66.9,108.86 66.8,108.76 66.6,108.76 66.5,108.86 66.5,109.1 66.28,109.32 65.9,109.32 65.68,109.1 65.68,108.86 65.58,108.76 65.38,108.76 65.28,108.86 65.28,109.1 65.06,109.32 64.69,109.32 64.47,109.1 64.47,108.86 64.36,108.76 64.16,108.76 64.06,108.86 64.06,109.1 63.84,109.32 63.47,109.32 63.25,109.1 63.25,108.86 63.14,108.76 62.94,108.76 62.84,108.86 62.84,109.1 62.62,109.32 62.25,109.32 62.03,109.1 62.03,108.86 61.93,108.76 61.72,108.76 61.62,108.86 61.62,109.1 61.4,109.32 61.03,109.32 60.81,109.1 60.81,108.86 60.71,108.76 60.5,108.76 60.4,108.86 60.4,109.1 60.18,109.32 59.81,109.32 59.59,109.1 59.59,108.86 59.49,108.76 59.28,108.76 59.18,108.86 59.18,109.1 58.96,109.32 58.59,109.32 58.37,109.1 58.37,108.86 58.27,108.76 58.06,108.76 57.96,108.86 57.96,109.1 57.74,109.32 57.37,109.32 57.15,109.1 57.15,108.86 57.05,108.76 56.85,108.76 56.74,108.86 56.74,109.1 56.52,109.32 56.15,109.32 55.93,109.1 55.93,108.86 55.83,108.76 55.63,108.76 55.52,108.86 55.52,109.1 55.3,109.32 54.93,109.32 54.71,109.1 54.71,108.86 54.61,108.76 54.41,108.76 54.31,108.86 54.31,109.1 54.08,109.32 53.71,109.32 53.49,109.1 53.49,108.86 53.39,108.76 53.19,108.76 53.09,108.86 53.09,109.1 52.87,109.32 52.49,109.32 52.27,109.1 52.27,108.86 52.17,108.76 51.97,108.76 51.87,108.86 51.87,109.1 51.65,109.32 51.27,109.32 51.05,109.1 51.05,108.86 50.95,108.76 50.75,108.76 50.65,108.86 50.65,109.1 50.43,109.32 50.06,109.32 49.83,109.1 49.83,108.86 49.73,108.76 49.53,108.76 49.43,108.86 49.43,109.1 49.21,109.32 48.84,109.32 48.62,109.1 48.62,108.86 48.51,108.76 48.31,108.76 48.21,108.86 48.21,109.1 47.99,109.32 47.62,109.32 47.4,109.1 47.4,108.86 47.29,108.76 47.09,108.76 46.99,108.86 46.99,109.1 46.77,109.32 46.4,109.32 46.18,109.1 46.18,108.86 46.08,108.76 15.4,108.76 14.12,110.05 10.33,110.05 10.06,109.78 10.06,105.02 10.33,104.75 11.53,104.75 v3(12.06,104.22)
  BOTTOM w0.102: FMC.E27 v3(12.06,104.22)
FMC_DQ+9: length 142.1
  TOP w0.102: U5.D10 v1(122.71,101.75)
  SIG2 w0.102: v1(122.71,101.75) 122.31,102.15 121.54,102.15 121.31,101.92 121.31,100.39 121.07,100.15 116.45,100.15 115.45,101.15 103.62,101.15 94.95,109.83 89.68,109.83 89.46,110.05 89.46,110.31 89.36,110.41 89.15,110.41 89.05,110.31 89.05,110.05 88.83,109.83 88.46,109.83 88.24,110.05 88.24,110.31 88.14,110.41 87.93,110.41 87.83,110.31 87.83,110.05 87.61,109.83 87.24,109.83 87.02,110.05 87.02,110.31 86.92,110.41 86.72,110.41 86.61,110.31 86.61,110.05 86.39,109.83 86.02,109.83 85.8,110.05 85.8,110.31 85.7,110.41 85.5,110.41 85.39,110.31 85.39,110.05 85.17,109.83 84.8,109.83 84.58,110.05 84.58,110.31 84.48,110.41 84.28,110.41 84.18,110.31 84.18,110.05 83.96,109.83 83.58,109.83 83.36,110.05 83.36,110.34 83.26,110.44 83.06,110.44 82.96,110.34 82.96,110.05 82.74,109.83 82.36,109.83 82.14,110.05 82.14,110.34 82.04,110.44 81.84,110.44 81.74,110.34 81.74,110.05 81.52,109.83 81.14,109.83 80.92,110.05 80.92,110.34 80.82,110.44 80.62,110.44 80.52,110.34 80.52,110.05 80.3,109.83 79.93,109.83 79.71,110.05 79.71,110.34 79.6,110.44 79.4,110.44 79.3,110.34 79.3,110.05 79.08,109.83 78.71,109.83 78.49,110.05 78.49,110.34 78.38,110.44 78.18,110.44 78.08,110.34 78.08,110.05 77.86,109.83 77.49,109.83 77.27,110.05 77.27,110.34 77.17,110.44 76.96,110.44 76.86,110.34 76.86,110.05 76.64,109.83 76.27,109.83 76.05,110.05 76.05,110.34 75.95,110.44 75.74,110.44 75.64,110.34 75.64,110.05 75.42,109.83 75.05,109.83 74.83,110.05 74.83,110.34 74.73,110.44 74.52,110.44 74.42,110.34 74.42,110.05 74.2,109.83 73.83,109.83 73.61,110.05 73.61,110.34 73.51,110.44 73.3,110.44 73.2,110.34 73.2,110.05 72.98,109.83 72.61,109.83 72.39,110.05 72.39,110.34 72.29,110.44 72.09,110.44 71.98,110.34 71.98,110.05 71.76,109.83 71.39,109.83 71.17,110.05 71.17,110.34 71.07,110.44 70.87,110.44 70.76,110.34 70.76,110.05 70.54,109.83 70.17,109.83 69.95,110.05 69.95,110.34 69.85,110.44 69.65,110.44 69.55,110.34 69.55,110.05 69.32,109.83 68.95,109.83 68.73,110.05 68.73,110.34 68.63,110.44 68.43,110.44 68.33,110.34 68.33,110.05 68.11,109.83 67.73,109.83 67.51,110.05 67.51,110.34 67.41,110.44 67.21,110.44 67.11,110.34 67.11,110.05 66.89,109.83 66.51,109.83 66.29,110.05 66.29,110.34 66.19,110.44 65.99,110.44 65.89,110.34 65.89,110.05 65.67,109.83 65.3,109.83 65.07,110.05 65.07,110.34 64.97,110.44 64.77,110.44 64.67,110.34 64.67,110.05 64.45,109.83 64.08,109.83 63.86,110.05 63.86,110.34 63.75,110.44 63.55,110.44 63.45,110.34 63.45,110.05 63.23,109.83 62.86,109.83 62.64,110.05 62.64,110.34 62.53,110.44 62.33,110.44 62.23,110.34 62.23,110.05 62.01,109.83 61.64,109.83 61.42,110.05 61.42,110.34 61.32,110.44 61.11,110.44 61.01,110.34 61.01,110.05 60.79,109.83 60.42,109.83 60.2,110.05 60.2,110.34 60.1,110.44 59.89,110.44 59.79,110.34 59.79,110.05 59.57,109.83 59.2,109.83 58.98,110.05 58.98,110.34 58.88,110.44 58.67,110.44 58.57,110.34 58.57,110.05 58.35,109.83 57.98,109.83 57.76,110.05 57.76,110.34 57.66,110.44 57.45,110.44 57.35,110.34 57.35,110.05 57.13,109.83 56.76,109.83 56.54,110.05 56.54,110.34 56.44,110.44 56.24,110.44 56.13,110.34 56.13,110.05 55.91,109.83 55.54,109.83 55.32,110.05 55.32,110.34 55.22,110.44 55.02,110.44 54.91,110.34 54.91,110.05 54.69,109.83 54.32,109.83 54.1,110.05 54.1,110.34 54,110.44 53.8,110.44 53.7,110.34 53.7,110.05 53.48,109.83 53.1,109.83 52.88,110.05 52.88,110.34 52.78,110.44 52.58,110.44 52.48,110.34 52.48,110.05 52.26,109.83 51.88,109.83 51.66,110.05 51.66,110.34 51.56,110.44 51.36,110.44 51.26,110.34 51.26,110.05 51.04,109.83 50.66,109.83 50.44,110.05 50.44,110.34 50.34,110.44 50.14,110.44 50.04,110.34 50.04,110.05 49.82,109.83 49.45,109.83 49.23,110.05 49.23,110.34 49.12,110.44 48.92,110.44 48.82,110.34 48.82,110.05 48.6,109.83 48.23,109.83 48.01,110.05 48.01,110.34 47.9,110.44 47.7,110.44 47.6,110.34 47.6,110.05 47.38,109.83 47.01,109.83 46.79,110.05 46.79,110.34 46.69,110.44 46.48,110.44 46.38,110.34 46.38,110.05 46.16,109.83 18.95,109.83 v3(18.41,109.3)
  BOTTOM w0.102: FMC.K31 v3(18.41,109.3)
FMC_DQ+10: length 142
  TOP w0.102: v1(114.72,97.74) U5.G2
  SIG1 w0.102: v1(114.72,97.74) 114.31,97.74 113.89,97.33 113.56,97.33 113.04,97.86 111.74,97.86 99.77,109.83 98.18,109.83 97.96,110.05 97.96,110.36 97.86,110.46 97.66,110.46 97.56,110.36 97.56,110.05 97.34,109.83 96.96,109.83 96.74,110.05 96.74,110.36 96.64,110.46 96.44,110.46 96.34,110.36 96.34,110.05 96.12,109.83 95.74,109.83 95.52,110.05 95.52,110.36 95.42,110.46 95.22,110.46 95.12,110.36 95.12,110.05 94.9,109.83 94.52,109.83 94.3,110.05 94.3,110.36 94.2,110.46 94,110.46 93.9,110.36 93.9,110.05 93.68,109.83 93.31,109.83 93.09,110.05 93.09,110.36 92.98,110.46 92.78,110.46 92.68,110.36 92.68,110.05 92.46,109.83 92.09,109.83 91.87,110.05 91.87,110.36 91.76,110.46 91.56,110.46 91.46,110.36 91.46,110.05 91.24,109.83 90.87,109.83 90.65,110.05 90.65,110.36 90.55,110.46 90.34,110.46 90.24,110.36 90.24,110.05 90.02,109.83 89.65,109.83 89.43,110.05 89.43,110.36 89.33,110.46 89.12,110.46 89.02,110.36 89.02,110.05 88.8,109.83 88.43,109.83 88.21,110.05 88.21,110.36 88.11,110.46 87.9,110.46 87.8,110.36 87.8,110.05 87.58,109.83 87.21,109.83 86.99,110.05 86.99,110.36 86.89,110.46 86.68,110.46 86.58,110.36 86.58,110.05 86.36,109.83 85.99,109.83 85.77,110.05 85.77,110.36 85.67,110.46 85.47,110.46 85.36,110.36 85.36,110.05 85.14,109.83 84.77,109.83 84.55,110.05 84.55,110.36 84.45,110.46 84.25,110.46 84.14,110.36 84.14,110.05 83.92,109.83 83.55,109.83 83.33,110.05 83.33,110.36 83.23,110.46 83.03,110.46 82.93,110.36 82.93,110.05 82.7,109.83 82.33,109.83 82.11,110.05 82.11,110.36 82.01,110.46 81.81,110.46 81.71,110.36 81.71,110.05 81.49,109.83 81.11,109.83 80.89,110.05 80.89,110.36 80.79,110.46 80.59,110.46 80.49,110.36 80.49,110.05 80.27,109.83 79.89,109.83 79.67,110.05 79.67,110.36 79.57,110.46 79.37,110.46 79.27,110.36 79.27,110.05 79.05,109.83 78.68,109.83 78.45,110.05 78.45,110.36 78.35,110.46 78.15,110.46 78.05,110.36 78.05,110.05 77.83,109.83 77.46,109.83 77.24,110.05 77.24,110.36 77.13,110.46 76.93,110.46 76.83,110.36 76.83,110.05 76.61,109.83 76.24,109.83 76.02,110.05 76.02,110.36 75.91,110.46 75.71,110.46 75.61,110.36 75.61,110.05 75.39,109.83 75.02,109.83 74.8,110.05 74.8,110.36 74.7,110.46 74.49,110.46 74.39,110.36 74.39,110.05 74.17,109.83 73.8,109.83 73.58,110.05 73.58,110.36 73.48,110.46 73.27,110.46 73.17,110.36 73.17,110.05 72.95,109.83 72.58,109.83 72.36,110.05 72.36,110.36 72.26,110.46 72.05,110.46 71.95,110.36 71.95,110.05 71.73,109.83 71.36,109.83 71.14,110.05 71.14,110.36 71.04,110.46 70.83,110.46 70.73,110.36 70.73,110.05 70.51,109.83 70.14,109.83 69.92,110.05 69.92,110.36 69.82,110.46 69.62,110.46 69.51,110.36 69.51,110.05 69.29,109.83 68.92,109.83 68.7,110.05 68.7,110.36 68.6,110.46 68.4,110.46 68.29,110.36 68.29,110.05 68.07,109.83 67.7,109.83 67.48,110.05 67.48,110.36 67.38,110.46 67.18,110.46 67.08,110.36 67.08,110.05 66.86,109.83 66.48,109.83 66.26,110.05 66.26,110.36 66.16,110.46 65.96,110.46 65.86,110.36 65.86,110.05 65.64,109.83 65.26,109.83 65.04,110.05 65.04,110.36 64.94,110.46 64.74,110.46 64.64,110.36 64.64,110.05 64.42,109.83 64.04,109.83 63.82,110.05 63.82,110.36 63.72,110.46 63.52,110.46 63.42,110.36 63.42,110.05 63.2,109.83 62.83,109.83 62.61,110.05 62.61,110.36 62.5,110.46 62.3,110.46 62.2,110.36 62.2,110.05 61.98,109.83 61.61,109.83 61.39,110.05 61.39,110.36 61.28,110.46 61.08,110.46 60.98,110.36 60.98,110.05 60.76,109.83 60.39,109.83 60.17,110.05 60.17,110.36 60.07,110.46 59.86,110.46 59.76,110.36 59.76,110.05 59.54,109.83 59.17,109.83 58.95,110.05 58.95,110.39 58.85,110.49 58.64,110.49 58.54,110.39 58.54,110.05 58.32,109.83 57.95,109.83 57.73,110.05 57.73,110.39 57.63,110.49 57.42,110.49 57.32,110.39 57.32,110.05 57.1,109.83 56.73,109.83 56.51,110.05 56.51,110.39 56.41,110.49 56.2,110.49 56.1,110.39 56.1,110.05 55.88,109.83 55.51,109.83 55.29,110.05 55.29,110.39 55.19,110.49 54.99,110.49 54.88,110.39 54.88,110.05 54.66,109.83 54.29,109.83 54.07,110.05 54.07,110.39 53.97,110.49 53.77,110.49 53.66,110.39 53.66,110.05 53.44,109.83 53.07,109.83 52.85,110.05 52.85,110.39 52.75,110.49 52.55,110.49 52.45,110.39 52.45,110.05 52.22,109.83 51.85,109.83 51.63,110.05 51.63,110.39 51.53,110.49 51.33,110.49 51.23,110.39 51.23,110.05 51.01,109.83 50.63,109.83 50.41,110.05 50.41,110.39 50.31,110.49 50.11,110.49 50.01,110.39 50.01,110.05 49.79,109.83 49.41,109.83 49.19,110.05 49.19,110.39 49.09,110.49 48.89,110.49 48.79,110.39 48.79,110.05 48.57,109.83 48.2,109.83 47.97,110.05 47.97,110.39 47.87,110.49 47.67,110.49 47.57,110.39 47.57,110.05 47.35,109.83 20.55,109.83 19.28,108.56 18.95,108.56 v3(18.41,108.03)
  BOTTOM w0.102: FMC.J30 v3(18.41,108.03)
FMC_DQ+11: length 142.1
  TOP w0.102: v1(116.72,96.74) U5.H4
  SIG2 w0.102: v1(116.72,96.74) 116.72,96.77 117.32,97.38 117.32,98.1 117.08,98.35 104.63,98.35 96.76,106.22 56.85,106.22 56.74,106.32 56.74,107.7 56.52,107.92 56.15,107.92 55.93,107.7 55.93,106.32 55.83,106.22 55.63,106.22 55.52,106.32 55.52,107.7 55.3,107.92 54.93,107.92 54.71,107.7 54.71,106.32 54.61,106.22 54.41,106.22 54.31,106.32 54.31,107.7 54.08,107.92 53.71,107.92 53.49,107.7 53.49,106.32 53.39,106.22 53.19,106.22 53.09,106.32 53.09,107.68 52.87,107.9 52.49,107.9 52.27,107.68 52.27,106.32 52.17,106.22 51.97,106.22 51.87,106.32 51.87,107.68 51.65,107.9 51.27,107.9 51.05,107.68 51.05,106.32 50.95,106.22 50.75,106.22 50.65,106.32 50.65,107.68 50.43,107.9 50.06,107.9 49.83,107.68 49.83,106.32 49.73,106.22 49.53,106.22 49.43,106.32 49.43,107.68 49.21,107.9 48.84,107.9 48.62,107.68 48.62,106.32 48.51,106.22 48.31,106.22 48.21,106.32 48.21,107.68 47.99,107.9 47.62,107.9 47.4,107.68 47.4,106.32 47.29,106.22 47.09,106.22 46.99,106.32 46.99,107.68 46.77,107.9 46.4,107.9 46.18,107.68 46.18,106.32 46.08,106.22 12.91,106.22 12.78,106.36 12.78,108.45 13.14,108.82 13.46,108.82 13.64,108.64 13.64,108.2 13.46,108.03 v3(13.34,108.03)
  BOTTOM w0.102: FMC.F31 v3(13.34,108.03)
FMC_DQ-0: length 142
  TOP w0.102: U5.D4 117.22,101.24 v1(116.71,101.75)
  SIG2 w0.102: v3(18.41,100.41) 17.88,99.87 13.03,99.87 12.8,100.1 12.8,100.71 12.37,101.14 9.14,101.14 8.99,101.3 8.99,110.13 9.96,111.1 46.16,111.1 46.38,111.32 46.38,111.53 46.48,111.63 46.69,111.63 46.79,111.53 46.79,111.32 47.01,111.1 47.38,111.1 47.6,111.32 47.6,111.53 47.7,111.63 47.9,111.63 48.01,111.53 48.01,111.32 48.23,111.1 48.6,111.1 48.82,111.32 48.82,111.53 48.92,111.63 49.12,111.63 49.23,111.53 49.23,111.32 49.45,111.1 49.82,111.1 50.04,111.32 50.04,111.53 50.14,111.63 50.34,111.63 50.44,111.53 50.44,111.32 50.66,111.1 51.04,111.1 51.26,111.32 51.26,111.53 51.36,111.63 51.56,111.63 51.66,111.53 51.66,111.32 51.88,111.1 52.26,111.1 52.48,111.32 52.48,111.53 52.58,111.63 52.78,111.63 52.88,111.53 52.88,111.32 53.1,111.1 53.48,111.1 53.7,111.32 53.7,111.53 53.8,111.63 54,111.63 54.1,111.53 54.1,111.32 54.32,111.1 54.69,111.1 54.91,111.32 54.91,111.53 55.02,111.63 55.22,111.63 55.32,111.53 55.32,111.32 55.54,111.1 55.91,111.1 56.13,111.32 56.13,111.53 56.24,111.63 56.44,111.63 56.54,111.53 56.54,111.32 56.76,111.1 57.13,111.1 57.35,111.32 57.35,111.53 57.45,111.63 57.66,111.63 57.76,111.53 57.76,111.32 57.98,111.1 58.35,111.1 58.57,111.32 58.57,111.53 58.67,111.63 58.88,111.63 58.98,111.53 58.98,111.32 59.2,111.1 59.57,111.1 59.79,111.32 59.79,111.53 59.89,111.63 60.1,111.63 60.2,111.53 60.2,111.32 60.42,111.1 60.79,111.1 61.01,111.32 61.01,111.53 61.11,111.63 61.32,111.63 61.42,111.53 61.42,111.32 61.64,111.1 94.79,111.1 103.74,102.15 116.31,102.15 v1(116.71,101.75)
  BOTTOM w0.102: FMC.J25 v3(18.41,100.41)
FMC_DQ-1: length 142.1
  TOP w0.102: U5.D5 118.22,101.24 v1(117.71,101.75)
  SIG1 w0.102: v1(117.71,101.75) 117.31,102.15 116.46,102.15 116.1,102.51 116.1,104.93 103.58,117.45 9.17,117.45 8.99,117.27 8.99,98.76 9.14,98.6 13.46,98.6 13.59,98.73 13.59,98.88 v3(13.34,99.14)
  BOTTOM w0.102: v3(13.34,99.14) FMC.F23
FMC_DQ-2: length 142.1
  TOP w0.102: U5.E5 118.22,100.24 v1(117.71,100.75)
  SIG2 w0.102: v3(12.06,96.58) 12.37,96.58 12.5,96.46 12.5,96.19 12.36,96.05 10.93,96.05 10.31,95.43 9.91,95.43 9.63,95.71 9.63,96.3 7.72,98.2 7.72,111.18 8.92,112.37 46.16,112.37 46.38,112.59 46.38,112.83 46.48,112.93 46.69,112.93 46.79,112.83 46.79,112.59 47.01,112.37 47.38,112.37 47.6,112.59 47.6,112.83 47.7,112.93 47.9,112.93 48.01,112.83 48.01,112.59 48.23,112.37 48.6,112.37 48.82,112.59 48.82,112.83 48.92,112.93 49.12,112.93 49.23,112.83 49.23,112.59 49.45,112.37 49.82,112.37 50.04,112.59 50.04,112.83 50.14,112.93 50.34,112.93 50.44,112.83 50.44,112.59 50.66,112.37 94.72,112.37 103.93,103.15 117.93,103.15 118.1,102.98 118.1,101.15 v1(117.71,100.75)
  BOTTOM w0.102: FMC.E22 v3(12.06,96.58)
FMC_DQ-3: length 142.2
  TOP w0.102: v1(117.72,97.74) U5.G5
  SIG2 w0.102: v3(13.34,101.68) 13.87,101.14 46.08,101.14 46.18,101.24 46.18,101.46 46.4,101.68 46.77,101.68 46.99,101.46 46.99,101.24 47.09,101.14 47.29,101.14 47.4,101.24 47.4,101.46 47.62,101.68 47.99,101.68 48.21,101.46 48.21,101.24 48.31,101.14 48.51,101.14 48.62,101.24 48.62,101.46 48.84,101.68 49.21,101.68 49.43,101.46 49.43,101.24 49.53,101.14 49.73,101.14 49.83,101.24 49.83,101.46 50.06,101.68 50.43,101.68 50.65,101.46 50.65,101.24 50.75,101.14 50.95,101.14 51.05,101.24 51.05,101.46 51.27,101.68 51.65,101.68 51.87,101.46 51.87,101.24 51.97,101.14 52.17,101.14 52.27,101.24 52.27,101.46 52.49,101.68 52.87,101.68 53.09,101.46 53.09,101.24 53.19,101.14 53.39,101.14 53.49,101.24 53.49,101.46 53.71,101.68 54.08,101.68 54.31,101.46 54.31,101.24 54.41,101.14 54.61,101.14 54.71,101.24 54.71,101.46 54.93,101.68 55.3,101.68 55.52,101.46 55.52,101.24 55.63,101.14 55.83,101.14 55.93,101.24 55.93,101.46 56.15,101.68 56.52,101.68 56.74,101.46 56.74,101.24 56.85,101.14 57.05,101.14 57.15,101.24 57.15,101.46 57.37,101.68 57.74,101.68 57.96,101.46 57.96,101.24 58.06,101.14 58.27,101.14 58.37,101.24 58.37,101.46 58.59,101.68 58.96,101.68 59.18,101.46 59.18,101.24 59.28,101.14 59.49,101.14 59.59,101.24 59.59,101.46 59.81,101.68 60.18,101.68 60.4,101.46 60.4,101.24 60.5,101.14 60.71,101.14 60.81,101.24 60.81,101.46 61.03,101.68 61.4,101.68 61.62,101.46 61.62,101.24 61.72,101.14 61.93,101.14 62.03,101.24 62.03,101.46 62.25,101.68 62.62,101.68 62.84,101.46 62.84,101.24 62.94,101.14 63.14,101.14 63.25,101.24 63.25,101.46 63.47,101.68 63.84,101.68 64.06,101.46 64.06,101.24 64.16,101.14 64.36,101.14 64.47,101.24 64.47,101.46 64.69,101.68 65.06,101.68 65.28,101.46 65.28,101.24 65.38,101.14 65.58,101.14 65.68,101.24 65.68,101.46 65.9,101.68 66.28,101.68 66.5,101.46 66.5,101.24 66.6,101.14 66.8,101.14 66.9,101.24 66.9,101.46 67.12,101.68 67.5,101.68 67.72,101.46 67.72,101.24 67.82,101.14 68.02,101.14 68.12,101.24 68.12,101.46 68.34,101.68 68.72,101.68 68.94,101.46 68.94,101.24 69.04,101.14 69.24,101.14 69.34,101.24 69.34,101.46 69.56,101.68 69.93,101.68 70.15,101.46 70.15,101.24 70.26,101.14 70.46,101.14 70.56,101.24 70.56,101.46 70.78,101.68 71.15,101.68 71.37,101.46 71.37,101.24 71.48,101.14 71.68,101.14 71.78,101.24 71.78,101.46 72,101.68 72.37,101.68 72.59,101.46 72.59,101.24 72.69,101.14 72.9,101.14 73,101.24 73,101.46 73.22,101.68 73.59,101.68 73.81,101.46 73.81,101.24 73.91,101.14 74.12,101.14 74.22,101.24 74.22,101.46 74.44,101.68 74.81,101.68 75.03,101.46 75.03,101.24 75.13,101.14 75.34,101.14 75.44,101.24 75.44,101.46 75.66,101.68 76.03,101.68 76.25,101.46 76.25,101.24 76.35,101.14 76.56,101.14 76.66,101.24 76.66,101.46 76.88,101.68 77.25,101.68 77.47,101.46 77.47,101.24 77.57,101.14 77.77,101.14 77.88,101.24 77.88,101.46 78.1,101.68 78.47,101.68 78.69,101.46 78.69,101.24 78.79,101.14 78.99,101.14 79.1,101.24 79.1,101.46 79.32,101.68 79.69,101.68 79.91,101.46 79.91,101.24 80.01,101.14 80.21,101.14 80.31,101.24 80.31,101.46 80.54,101.68 80.91,101.68 81.13,101.46 81.13,101.24 81.23,101.14 81.43,101.14 81.53,101.24 81.53,101.46 81.75,101.68 82.13,101.68 82.35,101.46 82.35,101.24 82.45,101.14 82.65,101.14 82.75,101.24 82.75,101.46 82.97,101.68 83.35,101.68 83.57,101.46 83.57,101.24 83.67,101.14 83.87,101.14 83.97,101.24 83.97,101.46 84.19,101.68 84.56,101.68 84.79,101.46 84.79,101.24 84.89,101.14 85.09,101.14 85.19,101.24 85.19,101.46 85.41,101.68 85.78,101.68 86,101.46 86,101.24 86.11,101.14 86.31,101.14 86.41,101.24 86.41,101.46 86.63,101.68 87,101.68 87.22,101.46 87.22,101.24 87.33,101.14 87.53,101.14 87.63,101.24 87.63,101.46 87.85,101.68 88.22,101.68 88.44,101.46 88.44,101.24 88.54,101.14 97.59,101.14 104.39,94.35 114.96,94.35 115.95,93.35 119.89,93.35 120.11,93.57 120.11,96.97 119.94,97.14 118.76,97.14 118.16,97.74 v1(117.72,97.74)
  BOTTOM w0.102: FMC.F26 v3(13.34,101.68)
FMC_DQ-4: length 142
  TOP w0.102: v1(116.71,100.75) 117.22,100.24 U5.E4
  SIG1 w0.102: v1(116.71,100.75) 116.11,101.35 115.54,101.35 115.1,101.79 115.1,103.94 102.86,116.18 57.97,116.18 57.75,116.4 57.75,116.71 57.64,116.81 57.44,116.81 57.34,116.71 57.34,116.4 57.12,116.18 56.75,116.18 56.53,116.4 56.53,116.71 56.42,116.81 56.22,116.81 56.12,116.71 56.12,116.4 55.9,116.18 55.53,116.18 55.31,116.4 55.31,116.71 55.21,116.81 55,116.81 54.9,116.71 54.9,116.4 54.68,116.18 54.31,116.18 54.09,116.4 54.09,116.71 53.99,116.81 53.78,116.81 53.68,116.71 53.68,116.4 53.46,116.18 53.09,116.18 52.87,116.4 52.87,116.71 52.77,116.81 52.56,116.81 52.46,116.71 52.46,116.4 52.24,116.18 51.87,116.18 51.65,116.4 51.65,116.71 51.55,116.81 51.34,116.81 51.24,116.71 51.24,116.4 51.02,116.18 50.65,116.18 50.43,116.4 50.43,116.71 50.33,116.81 50.13,116.81 50.02,116.71 50.02,116.4 49.8,116.18 49.43,116.18 49.21,116.4 49.21,116.71 49.11,116.81 48.91,116.81 48.8,116.71 48.8,116.4 48.58,116.18 48.21,116.18 47.99,116.4 47.99,116.71 47.89,116.81 47.69,116.81 47.59,116.71 47.59,116.4 47.37,116.18 46.99,116.18 46.77,116.4 46.77,116.71 46.67,116.81 46.47,116.81 46.37,116.71 46.37,116.4 46.15,116.18 10.38,116.18 10.26,116.06 10.26,101.3 10.41,101.14 12.06,101.14 12.24,101.32 12.24,101.5 v3(12.06,101.68)
  BOTTOM w0.102: FMC.E25 v3(12.06,101.68)
